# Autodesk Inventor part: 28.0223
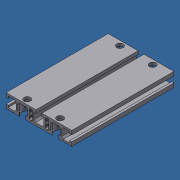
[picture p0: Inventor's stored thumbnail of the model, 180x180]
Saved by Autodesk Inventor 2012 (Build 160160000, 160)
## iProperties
Company: F
Created: 2007-06
Part Number: 28.0223
Material: Aluminum-6061
Document SubType Name: Modeling
Designer: Andy Moles
Density: 2.71 g/cm^3
Mass: 271.791 g
Surface Area: 680.952 cm^2
Volume: 100.292 cm^3
Description: L = 5.512" MILL TO 28.0223
Stock Number: 20.0995 PROFILE 90X19
Vendor: F
Author: Andy Moles
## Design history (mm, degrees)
sketch "Sketch1"
  geometry: L1 (18.4, -9.5)-(18.4, -5) reference; L2 (17.9, -5)-(15.7, -5) reference; L3 (15.7, -5)-(15.7, 3.5) reference; L4 (15.7, 3.5)-(18, 5.8) reference; L5 (18, 5.8)-(27, 5.8) reference; L6 (27, 5.8)-(29.3, 3.5) reference; L7 (29.3, 3.5)-(29.3, -5) reference; L8 (26.6, -5)-(26.6, -9.5) reference; L9 (45, -9.5)-(26.9, -9.5) reference; L10 (45, -4.1)-(45, -9.5) reference; L11 (45, -4.1)-(42, -4.1) reference; L12 (42, -4.6)-(42, -6.8) reference; L13 (42, -6.8)-(33.5, -6.8) reference; L14 (33.5, -6.8)-(31.2, -4.5) reference; L15 (31.2, -4.5)-(31.2, 4.5) reference; L16 (31.2, 4.5)-(33.5, 6.8) reference; L17 (33.5, 6.8)-(42, 6.8) reference; L18 (42, 4.1)-(45, 4.1) reference; L19 (45, 9.5)-(45, 4.1) reference; L20 (4.4, 9.5)-(45, 9.5) reference; L21 (4.1, 9.5)-(4.1, 5) reference; L22 (4.6, 5)-(6.8, 5) reference; L23 (6.8, 5)-(6.8, -3.5) reference; L24 (6.8, -3.5)-(4.5, -5.8) reference; L25 (4.5, -5.8)-(-4.5, -5.8) reference; L26 (-4.5, -5.8)-(-6.8, -3.5) reference; L27 (-6.8, -3.5)-(-6.8, 5) reference; L28 (-4.1, 5)-(-4.1, 9.5) reference; L29 (-45, 4.1)-(-45, 9.5) reference; L30 (-45, 4.1)-(-42, 4.1) reference; L31 (-42, 4.1)-(-42, 6.8) reference; L32 (-42, 6.8)-(-33.5, 6.8) reference; L33 (-33.5, 6.8)-(-31.2, 4.5) reference; L34 (-31.2, 4.5)-(-31.2, -4.5) reference; L35 (-31.2, -4.5)-(-33.5, -6.8) reference; L36 (-33.5, -6.8)-(-42, -6.8) reference; L37 (-42, -6.8)-(-42, -4.1) reference; L38 (-42, -4.1)-(-45, -4.1) reference; L39 (-45, -9.5)-(-45, -4.1) reference; L40 (-26.6, -9.5)-(-26.6, -5) reference; L41 (-29.3, -5)-(-29.3, 3.5) reference; L42 (-29.3, 3.5)-(-27, 5.8) reference; L43 (-27, 5.8)-(-18, 5.8) reference; L44 (-18, 5.8)-(-15.7, 3.5) reference; L45 (-15.7, 3.5)-(-15.7, -5) reference; L46 (-15.7, -5)-(-17.9, -5) reference; L47 (-18.4, -5)-(-18.4, -9.5) reference; L48 (-18.1, -9.5)-(-18.4, -9.5) reference; L49 (-26.6, -9.5)-(-45, -9.5) reference; L50 (-17.9, -5)-(-18.4, -5) reference; L51 (-26.6, -5)-(-29.3, -5) reference; L52 (-6.8, 5)-(-4.1, 5) reference; L53 (4.1, 5)-(4.6, 5) reference; L54 (-45, 9.5)-(-4.1, 9.5) reference; L55 (4.1, 9.5)-(4.4, 9.5) reference; L56 (29.3, -5)-(26.6, -5) reference; L57 (18.4, -5)-(17.9, -5) reference; L58 (26.9, -9.5)-(26.6, -9.5) reference; L59 (18.4, -9.5)-(-18.1, -9.5) reference; L60 (42, 6.8)-(42, 4.1) reference; L61 (42, -4.1)-(42, -4.6) reference; L62 (-13.3, 3.657)-(-13.3, 5); L63 (-12.646, 2.59)-(-13.007, 2.95); L64 (-11.3, 7)-(-10.7, 7)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; A1 r 1 centre (-12.3, 3.657) between (-13.3, 3.657) and (-13.007, 2.95); A2 r 0.5 centre (-13, 2.236) between (-12.667, 1.863) and (-12.646, 2.59); A3 r 2 centre (-11.3, 5) between (-11.3, 7) and (-13.3, 5); A4 r 0.5 centre (-9, 2.236) between (-9.354, 2.59) and (-9.333, 1.863); A5 r 1 centre (-9.7, 3.657) between (-8.993, 2.95) and (-8.7, 3.657); A6 r 2 centre (-10.7, 5) between (-8.7, 5) and (-10.7, 7); A7 r 2 centre (-10.7, -5) between (-10.7, -7) and (-8.7, -5); A8 r 2 centre (-11.3, -5) between (-13.3, -5) and (-11.3, -7); A9 r 2.5 centre (-11, 0) between (-12.667, 1.863) and (-12.667, -1.863); A10 r 2.5 centre (-11, 0) between (-9.333, -1.863) and (-9.333, 1.863); A11 r 0.5 centre (-9, -2.236) between (-9.333, -1.863) and (-9.354, -2.59); A12 r 1 centre (-9.7, -3.657) between (-8.7, -3.657) and (-8.993, -2.95); A13 r 1 centre (-12.3, -3.657) between (-13.007, -2.95) and (-13.3, -3.657); A14 r 0.5 centre (-13, -2.236) between (-12.646, -2.59) and (-12.667, -1.863); A15 r 1 centre (12.3, 3.657) between (13.007, 2.95) and (13.3, 3.657); A16 r 0.5 centre (13, 2.236) between (12.646, 2.59) and (12.667, 1.863); A17 r 2 centre (11.3, 5) between (13.3, 5) and (11.3, 7); A18 r 0.5 centre (9, 2.236) between (9.333, 1.863) and (9.354, 2.59); A19 r 1 centre (9.7, 3.657) between (8.7, 3.657) and (8.993, 2.95); A20 r 2 centre (10.7, 5) between (10.7, 7) and (8.7, 5); A21 r 1 centre (9.7, -3.657) between (8.993, -2.95) and (8.7, -3.657); A22 r 2.5 centre (11, 0) between (9.333, 1.863) and (9.333, -1.863); A23 r 0.5 centre (9, -2.236) between (9.354, -2.59) and (9.333, -1.863); A24 r 2 centre (10.7, -5) between (8.7, -5) and (10.7, -7); A25 r 2.5 centre (11, 0) between (12.667, -1.863) and (12.667, 1.863); A26 r 0.5 centre (13, -2.236) between (12.667, -1.863) and (12.646, -2.59); A27 r 1 centre (12.3, -3.657) between (13.3, -3.657) and (13.007, -2.95); A28 r 2 centre (11.3, -5) between (11.3, -7) and (13.3, -5)
  constraints: 162 end point, 56 point on circle, 28 centre point, 28 horizontal, 23 vertical, 71 other
  dimensions: "d14" = 34.00003 distance from line of A9.centre L29
extrude "Extrusion1" new body sketch "Sketch1" stored distance "d0" = 140; taper "d1" = 0 deg
sketch "Sketch2"
  geometry: L1 (0, -140)-(36.8, -140) reference; L2 (63.4, -140)-(63.4, 0) reference; 6 further points
  constraints: 2 horizontal alignment, 2 vertical alignment
  dimensions: "d2" = 140 distance of L1.end point (36.8, 0) (derived); "d3" = 127 distance of point (40.9, -133.5) point (40.9, -6.5); "d4" = 6.5 distance from line of point (40.9, -133.5) L1 (= -0.5 x d3 + 0.5 x d2); "d5" = 22.5 distance from line of point (40.9, -6.5) L2; "d6" = 67.5 distance from line of point (-4.1, -6.5) L2
hole "Hole1" sketch "Sketch2" at (40.9, -6.5), (-4.1, -6.5), (-4.1, -133.5), (40.9, -133.5) diameter "d7" = 9; stored, may be unused: countersink angle "d11" = 90 deg, drill point angle "d13" = 118 deg; dims "d8" = 6, "d9" = 15, "d10" = 15.3, "d12" = 8
body "Solid1"
